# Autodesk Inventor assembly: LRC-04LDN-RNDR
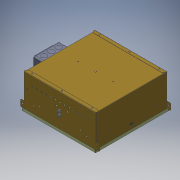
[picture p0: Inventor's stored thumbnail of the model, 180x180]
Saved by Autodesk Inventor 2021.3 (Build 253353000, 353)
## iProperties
load_classification: Lighting
motor: 0 ul
Part Number: LRC-04LDN-RNDR
Document SubType Name: Assembly
Designer: JChurch
description: 0:0:Regressed Lens 4" Downlight - COB LED
manufacturer: 0:0:The Kirlin Company
model: 0:0:LRC-04LDN
url: 0:0:
Author: JChurch
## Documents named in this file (6)
- X:\Revit Files\0000-Un-Zipped\COB\LRC-04LDN-RND\LRC-04LDN-RNDR.iam
- X:\INVENTOR\830\830520-00-00.ipt
- X:\INVENTOR\881\881088-00-00.iam
- X:\INVENTOR\750\750031-00-XX.iam
- X:\INVENTOR\725\725377-00-00.ipt
- X:\Revit Files\0000-Un-Zipped\COB\LRC-04LDN-RND\LRC-04LDN-RNDR_Substitute_1.ipt
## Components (5 placed, 5 different names)
1. 830520-00-00:1 — Mate:1, Mate:2, Mate:3, Mate:4, Tangent:1, Angle:1, Insert:2
2. 881088-00-00:1 [sub-assembly] — Mate:4, Tangent:1, Angle:1
3. 750031-00-XX:1 [sub-assembly] — Insert:1, Insert:2
4. 725377-00-00:1 — Insert:1
5. LRC-04LDN-RNDR_Substitute_1:1
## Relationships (8: Mate 4, Insert 2, Tangent 1, Angle 1)
- Mate:1: 830520-00-00:1
- Mate:2: 830520-00-00:1
- Mate:3: 830520-00-00:1
- Mate:4: 830520-00-00:1 ↔ 881088-00-00:1
- Tangent:1: 830520-00-00:1 ↔ 881088-00-00:1
- Angle:1: 830520-00-00:1 ↔ 881088-00-00:1
- Insert:1: 750031-00-XX:1 ↔ 725377-00-00:1
- Insert:2: 830520-00-00:1 ↔ 750031-00-XX:1
